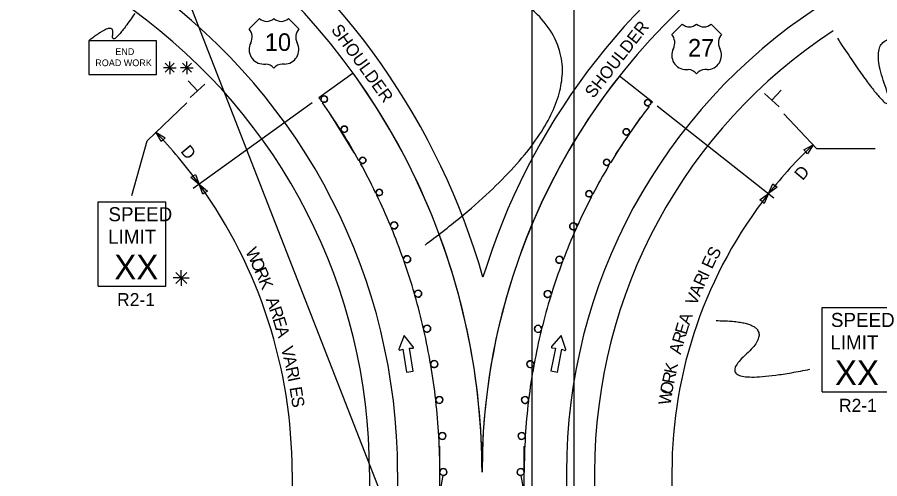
# Model space of a CAD drawing. Extents: x 16486 to 19506, y 5576 to 7023.
# Drawn here: x 16687.6 to 17178.1, y 6501.5 to 6764 of the extents above; entities that cross this region are included whole.
import ezdxf

# ---------------------------------------------------------------- set-up
doc = ezdxf.new("R2010")
doc.units = 0
for name, color, linetype in [('ALI_LEGAL_EX', 7, 'Continuous'), ('Level 3', 7, 'Continuous'), ('MT_SCRATCH_LEVEL_A', 7, 'Continuous'), ('MT_SCRATCH_LEVEL_E', 7, 'Continuous'), ('PAVT_EDGE_EX', 7, 'Continuous'), ('TRAFFIC_SIGNS_PR', 7, 'Continuous'), ('TYPICAL_EX', 7, 'Continuous'), ('TYPICAL_TEXT_DIMEN_PR', 7, 'Continuous')]:
    doc.layers.add(name, color=color, linetype=linetype)

msp = doc.modelspace()

# ---------------------------------------------------------------- linework, layer by layer
at = {"layer": 'ALI_LEGAL_EX'}
for p, q in [((16687.64, 7022.55), (16909.67, 6454.18)), ((16980.24, 6998.86), (16980.24, 6180.72)), ((17004.24, 6998.86), (17004.24, 6180.72)), ((16980.24, 6946.95), (16980.24, 6083.04)), ((17004.24, 6946.95), (17004.24, 6083.04))]:
    msp.add_line(p, q, dxfattribs=at)
for points in [[(16879.14, 6687.34), (16865.91, 6708.56)], [(16879.14, 6687.34), (16865.91, 6708.56)], [(17028.03, 6686.21), (17042.15, 6706.84)], [(17028.03, 6686.21), (17042.15, 6706.84)], [(16927.96, 6495.08), (16927.96, 6520.08)], [(16975.96, 6495.08), (16975.96, 6520.08)]]:
    msp.add_lwpolyline(points, dxfattribs=at)
at = {"layer": 'Level 3'}
msp.add_line((16843.96, 6505.27), (16843.96, 6497.36), dxfattribs=at)
at = {"layer": 'MT_SCRATCH_LEVEL_A'}
for points in [[(16878.71, 6732.17), (16859.24, 6718.13)], [(17048.92, 6715.72), (17030.07, 6730.57)], [(16859.73, 6717.44), (16860.41, 6717.44)], [(16861.61, 6715.71), (16861.18, 6715.41)], [(17047.92, 6715.51), (17048.77, 6715.53)], [(17047.03, 6713.3), (17046.58, 6713.66)], [(16871.46, 6700.06), (16871.86, 6700.32)], [(16872.87, 6698.7), (16872.47, 6698.45)], [(17035.06, 6696.83), (17034.64, 6697.12)], [(17035.78, 6698.8), (17036.21, 6698.5)], [(16881.95, 6682.41), (16882.33, 6682.62)], [(16883.16, 6681.09), (16882.8, 6680.89)], [(17024.66, 6681.5), (17025.05, 6681.26)], [(17024.1, 6679.68), (17023.71, 6679.91)], [(16891.44, 6664.19), (16891.78, 6664.35)], [(16892.46, 6662.95), (16892.12, 6662.78)], [(17014.19, 6661.91), (17013.83, 6662.09)], [(17014.6, 6663.56), (17014.96, 6663.37)], [(16899.86, 6645.53), (16900, 6645.59)], [(16900.59, 6644.18), (16900.44, 6644.12)], [(17005.33, 6643.5), (17005.17, 6643.57)], [(17005.83, 6645.05), (17005.99, 6644.98)], [(16907.24, 6626.34), (16907.35, 6626.37)], [(16907.78, 6625.13), (16907.68, 6625.09)], [(16997.62, 6624.68), (16997.5, 6624.72)], [(16997.99, 6626.04), (16998.11, 6625.99)], [(16913.53, 6606.76), (16913.61, 6606.78)], [(16913.91, 6605.72), (16913.83, 6605.7)], [(16991.05, 6605.43), (16990.96, 6605.46)], [(16991.31, 6606.59), (16991.4, 6606.56)], [(16918.7, 6586.85), (16918.76, 6586.87)], [(16918.95, 6586), (16918.9, 6585.99)], [(16985.64, 6585.83), (16985.59, 6585.85)], [(16985.81, 6586.77), (16985.87, 6586.75)], [(16922.74, 6566.69), (16922.78, 6566.69)], [(16922.89, 6566.04), (16922.86, 6566.03)], [(16981.42, 6565.94), (16981.38, 6565.95)], [(16981.51, 6566.65), (16981.55, 6566.65)], [(16925.64, 6546.33), (16925.66, 6546.33)], [(16925.71, 6545.89), (16925.69, 6545.88)], [(16978.39, 6545.84), (16978.37, 6545.84)], [(16978.43, 6546.32), (16978.45, 6546.31)], [(16927.38, 6525.83), (16927.39, 6525.83)], [(16927.4, 6525.61), (16927.39, 6525.61)], [(16976.57, 6525.59), (16976.56, 6525.59)], [(16976.58, 6525.83), (16976.58, 6525.83)], [(16927.96, 6505.27), (16927.97, 6505.27)], [(16975.96, 6505.27), (16975.96, 6505.27)], [(16929.62, 6503.3), (16927.96, 6493.83), (16975.96, 6493.83), (16974.3, 6503.3)]]:
    msp.add_lwpolyline(points, dxfattribs=at)
for centre, radius, start, end in [((16563.96, 6505.27), 388, 22.8554, 35.7873), ((17315.96, 6505.27), 364, 141.7598, 180), ((16563.96, 6505.27), 364, 35.6537, 35.7873), ((16862.21, 6717.41), 1.8, 0, 179.0978), ((16563.96, 6505.27), 364, 32.3536, 35.2603), ((16862.21, 6717.41), 1.8, 250.5205, 0), ((17046.13, 6715.4), 1.8, 3.5129, 180), ((17046.13, 6715.4), 1.8, 180, 284.5518), ((17315.96, 6505.27), 340, 141.7598, 141.7992), ((17315.96, 6505.27), 340, 142.2759, 145.3661), ((16873.66, 6700.32), 1.8, 0, 180), ((17033.98, 6698.8), 1.8, 0, 180), ((16563.96, 6505.27), 364, 29.1198, 32.0533), ((16873.66, 6700.32), 1.8, 244.1065, 0), ((17315.96, 6505.27), 340, 145.7074, 148.8275), ((17033.98, 6698.8), 1.8, 180, 291.4148), ((16884.13, 6682.62), 1.8, 0, 180), ((16563.96, 6505.27), 364, 25.8855, 28.8467), ((16884.13, 6682.62), 1.8, 237.6934, 0), ((17022.86, 6681.5), 1.8, 0, 180), ((17022.86, 6681.5), 1.8, 180, 298.2766), ((17315.96, 6505.27), 340, 149.1383, 152.2895), ((16893.58, 6664.35), 1.8, 0, 180), ((16563.96, 6505.27), 364, 22.663, 25.6406), ((16893.58, 6664.35), 1.8, 231.2811, 0), ((17315.96, 6505.27), 340, 152.5687, 155.7382), ((17012.8, 6663.56), 1.8, 0, 180), ((17012.8, 6663.56), 1.8, 180, 305.1374), ((16563.96, 6505.27), 388, 0, 22.8554), ((16563.96, 6505.27), 388, 0, 22.8554), ((16563.96, 6505.27), 388, 0, 22.8554), ((16902, 6645.59), 2, 0, 180), ((17003.83, 6645.05), 2, 0, 180), ((16563.96, 6505.27), 364, 19.4261, 22.4229), ((16902, 6645.59), 2, 224.8459, 0), ((17315.96, 6505.27), 340, 156.0121, 159.2032), ((17003.83, 6645.05), 2, 180, 312.0242), ((16909.35, 6626.37), 2, 0, 180), ((16995.99, 6626.04), 2, 0, 180), ((16563.96, 6505.27), 364, 16.189, 19.219), ((16909.35, 6626.37), 2, 218.4379, 0), ((17315.96, 6505.27), 340, 159.4399, 162.6687), ((16995.99, 6626.04), 2, 180, 318.8797), ((16915.61, 6606.78), 2, 0, 180), ((16989.31, 6606.59), 2, 0, 180), ((16563.96, 6505.27), 364, 12.9515, 16.0153), ((16915.61, 6606.78), 2, 212.0306, 0), ((17315.96, 6505.27), 340, 162.8672, 166.1345), ((16989.31, 6606.59), 2, 180, 325.7344), ((16920.75, 6586.87), 2, 0, 180), ((16983.81, 6586.77), 2, 0, 180), ((16563.96, 6505.27), 364, 9.7138, 12.8119), ((16920.75, 6586.87), 2, 205.6238, 0), ((17315.96, 6505.27), 340, 166.2942, 169.6006), ((16983.81, 6586.77), 2, 180, 332.5884), ((16924.78, 6566.69), 2, 0, 180), ((16979.51, 6566.65), 2, 0, 180), ((16563.96, 6505.27), 364, 6.476, 9.6087), ((16924.78, 6566.69), 2, 199.2175, 0), ((16979.51, 6566.65), 2, 180, 339.4418), ((17315.96, 6505.27), 340, 169.7209, 173.067), ((16927.66, 6546.33), 2, 0, 180), ((16563.96, 6505.27), 364, 3.238, 6.4057), ((16927.66, 6546.33), 2, 192.8115, 0), ((16976.43, 6546.32), 2, 0, 180), ((16976.43, 6546.32), 2, 180, 346.2947), ((17315.96, 6505.27), 340, 173.1474, 176.5334), ((16929.39, 6525.83), 2, 0, 180), ((16563.96, 6505.27), 364, 0, 3.2028), ((16929.39, 6525.83), 2, 186.4057, 0), ((16974.58, 6525.83), 2, 0, 180), ((16974.58, 6525.83), 2, 180, 353.1474), ((17315.96, 6505.27), 340, 176.5737, 180), ((16929.97, 6505.27), 2, 0, 180), ((16929.97, 6505.27), 2, 260.0595, 0), ((16973.96, 6505.27), 2, 0, 180), ((16973.96, 6505.27), 2, 180, 279.941)]:
    msp.add_arc(centre, radius, start, end, dxfattribs=at)
at = {"layer": 'MT_SCRATCH_LEVEL_E'}
for p, q in [((16907.63, 6583.04), (16904.71, 6575.24)), ((16912.87, 6576.54), (16907.63, 6583.04)), ((16996.96, 6582.95), (16991.53, 6576.64)), ((16999.63, 6575.05), (16996.96, 6582.95)), ((16905.29, 6574.64), (16907, 6575.23)), ((16907, 6575.23), (16909.09, 6562.14)), ((16912.78, 6562.73), (16910.7, 6575.82)), ((16910.7, 6575.82), (16912.5, 6575.79)), ((16993.67, 6575.84), (16991.12, 6562.83)), ((16991.87, 6575.87), (16993.67, 6575.84)), ((16994.79, 6562.11), (16997.34, 6575.12)), ((16997.34, 6575.12), (16999.03, 6574.47)), ((16909.09, 6562.14), (16912.78, 6562.73)), ((16991.12, 6562.83), (16994.79, 6562.11))]:
    msp.add_line(p, q, dxfattribs=at)
for centre, start, end in [((16905.15, 6575.08), 159.4773, 289.0163), ((16912.5, 6576.25), 269.0886, 38.8256), ((16991.88, 6576.34), 139.3091, 268.8481), ((16999.18, 6574.91), 248.9205, 18.6574)]:
    msp.add_arc(centre, 0.463, start, end, dxfattribs=at)
at = {"layer": 'PAVT_EDGE_EX'}
for p, q in [((16887.96, 6505.27), (16887.96, 6073.13)), ((16903.96, 6505.27), (16903.96, 6073.13)), ((16999.96, 6505.27), (16999.96, 6073.13)), ((17015.96, 6505.27), (17015.96, 6073.13))]:
    msp.add_line(p, q, dxfattribs=at)
for centre, radius, start, end in [((16563.96, 6505.27), 404, 15.917, 54.2283), ((17315.96, 6505.27), 380, 123.1879, 163.0483), ((16563.96, 6505.27), 388, 0, 54.2283), ((17315.96, 6505.27), 364, 123.1879, 180), ((16563.96, 6505.27), 340, 0, 54.2283), ((17315.96, 6505.27), 316, 123.1879, 180), ((16563.96, 6505.27), 324, 0, 54.2283), ((17315.96, 6505.27), 300, 123.1879, 180), ((17315.96, 6505.27), 300, 180, 180.00000277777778)]:
    msp.add_arc(centre, radius, start, end, dxfattribs=at)
at = {"layer": 'TRAFFIC_SIGNS_PR'}
for p, q in [((16733.73, 6659.1), (16772.13, 6659.1)), ((16733.73, 6611.1), (16733.73, 6659.1)), ((16772.13, 6611.1), (16772.13, 6659.1)), ((16733.73, 6611.1), (16772.13, 6611.1)), ((17145.34, 6598.96), (17183.74, 6598.96)), ((17145.34, 6550.96), (17145.34, 6598.96)), ((17145.34, 6550.96), (17183.74, 6550.96))]:
    msp.add_line(p, q, dxfattribs=at)
msp.add_lwpolyline([(16728.41, 6731.44), (16766.81, 6731.44), (16766.81, 6750.64), (16728.41, 6750.64)], close=True, dxfattribs=at)
for centre, radius in [((16862.21, 6717.41), 1.8), ((17046.13, 6715.4), 1.8), ((16873.66, 6700.32), 1.8), ((17033.98, 6698.8), 1.8), ((16884.13, 6682.62), 1.8), ((17022.86, 6681.5), 1.8), ((16893.58, 6664.35), 1.8), ((17012.8, 6663.56), 1.8), ((16902, 6645.59), 2), ((17003.83, 6645.05), 2), ((16909.35, 6626.37), 2), ((16995.99, 6626.04), 2), ((16915.61, 6606.78), 2), ((16989.31, 6606.59), 2), ((16920.75, 6586.87), 2), ((16983.81, 6586.77), 2), ((16924.78, 6566.69), 2), ((16979.51, 6566.65), 2), ((16927.66, 6546.33), 2), ((16976.43, 6546.32), 2), ((16929.39, 6525.83), 2), ((16974.58, 6525.83), 2), ((16929.97, 6505.27), 2), ((16973.96, 6505.27), 2)]:
    msp.add_circle(centre, radius, dxfattribs=at)
at = {"layer": 'TYPICAL_EX'}
for p, q in [((16819.47, 6757.43), (16825.37, 6763.33)), ((16847.77, 6757.43), (16841.88, 6763.33)), ((17059.84, 6754.25), (17065.74, 6760.14)), ((17088.14, 6754.25), (17082.25, 6760.14)), ((16827.72, 6737.37), (16828.9, 6737.37)), ((16839.53, 6737.37), (16838.35, 6737.37)), ((17068.09, 6734.19), (17069.27, 6734.19)), ((17079.9, 6734.19), (17078.72, 6734.19))]:
    msp.add_line(p, q, dxfattribs=at)
for centre, radius, start, end in [((16829.5, 6767.62), 5.96, 226.1404, 313.8596), ((16837.75, 6767.62), 5.96, 226.1404, 313.8596), ((17069.87, 6764.44), 5.96, 226.1404, 313.8596), ((17078.12, 6764.44), 5.96, 226.1404, 313.8596), ((16813.89, 6752.71), 7.31, 333.0977, 40.1936), ((16853.36, 6752.71), 7.31, 139.8064, 206.9023), ((17054.26, 6749.53), 7.31, 333.0977, 40.1936), ((17093.73, 6749.53), 7.31, 139.8064, 206.9023), ((16827.73, 6745.61), 8.24, 152.6698, 269.9013), ((16839.51, 6745.61), 8.24, 270.0987, 27.3302), ((17068.1, 6742.43), 8.24, 152.6698, 269.9013), ((17079.88, 6742.43), 8.24, 270.0987, 27.3302), ((16828.91, 6731.46), 5.91, 37.1038, 90.1385), ((16838.33, 6731.46), 5.91, 89.8615, 142.8962), ((17069.28, 6728.28), 5.91, 37.1038, 90.1385), ((17078.7, 6728.28), 5.91, 89.8615, 142.8962)]:
    msp.add_arc(centre, radius, start, end, dxfattribs=at)
at = {"layer": 'TYPICAL_TEXT_DIMEN_PR'}
for p, q in [((16774.36, 6735.26), (16770.73, 6735.26)), ((16771.81, 6737.81), (16776.91, 6732.71)), ((16776.91, 6737.81), (16771.81, 6732.71)), ((16774.36, 6735.26), (16774.36, 6738.82)), ((16774.36, 6735.26), (16776.91, 6735.26)), ((16774.36, 6735.26), (16777.94, 6735.26)), ((16774.36, 6735.26), (16774.36, 6731.66)), ((16784.1, 6735.26), (16780.47, 6735.26)), ((16781.55, 6737.81), (16786.65, 6732.71)), ((16786.65, 6737.81), (16781.55, 6732.71)), ((16784.1, 6735.26), (16784.1, 6738.82)), ((16784.1, 6735.26), (16786.65, 6735.26)), ((16784.1, 6735.26), (16787.68, 6735.26)), ((16784.1, 6735.26), (16784.1, 6731.66)), ((16790.19, 6722.15), (16784.91, 6727.87)), ((16794.32, 6725.97), (16786.06, 6718.34)), ((17120.89, 6712.97), (17112.65, 6720.63)), ((17116.77, 6716.8), (17122.07, 6722.51)), ((16783.99, 6715.23), (16761.5, 6693.76)), ((16855.45, 6715.4), (16787.66, 6666.53)), ((17051.63, 6713.58), (17117.9, 6661.36)), ((17123.65, 6709.11), (17142.26, 6689.38)), ((16769.45, 6693.24), (16766.54, 6698.57)), ((16766.54, 6698.57), (16771.72, 6695.41)), ((16752.8, 6662.58), (16761.5, 6693.76)), ((16770.58, 6694.33), (16769.45, 6693.24)), ((16771.72, 6695.41), (16770.58, 6694.33)), ((17134.94, 6688.6), (17140.28, 6691.48)), ((17140.28, 6691.48), (17137.1, 6686.31)), ((17136.02, 6687.46), (17134.94, 6688.6)), ((17137.1, 6686.31), (17136.02, 6687.46)), ((17142.26, 6689.38), (17175.46, 6689.38)), ((17142.26, 6689.38), (17175.46, 6689.38)), ((17142.26, 6689.38), (17175.46, 6689.38)), ((16786.44, 6672.79), (16787.71, 6673.71)), ((16791.14, 6668.95), (16786.44, 6672.79)), ((16787.71, 6673.71), (16788.99, 6674.62)), ((16788.99, 6674.62), (16791.14, 6668.95)), ((16793.24, 6663.33), (16791.08, 6669)), ((16791.08, 6669), (16795.78, 6665.16)), ((17114.89, 6663.73), (17117.29, 6669.3)), ((17119.76, 6667.36), (17114.89, 6663.73)), ((17117.29, 6669.3), (17118.52, 6668.33)), ((17118.52, 6668.33), (17119.76, 6667.36)), ((16794.51, 6664.24), (16793.24, 6663.33)), ((16795.78, 6665.16), (16794.51, 6664.24)), ((17110.03, 6660.09), (17114.89, 6663.73)), ((17114.89, 6663.73), (17112.5, 6658.15)), ((17111.27, 6659.12), (17110.03, 6660.09)), ((17112.5, 6658.15), (17111.27, 6659.12)), ((17006.48, 6646.05), (17004.65, 6646.88)), ((16777.73, 6618.9), (16784.11, 6612.52)), ((16784.11, 6618.9), (16777.73, 6612.52)), ((16780.92, 6615.71), (16780.92, 6620.17)), ((16780.92, 6615.71), (16776.39, 6615.71)), ((16780.92, 6615.71), (16784.11, 6615.71)), ((16780.92, 6615.71), (16785.4, 6615.71)), ((16780.92, 6615.71), (16780.92, 6611.21)), ((17059.96, 6505.27), (17059.96, 6493.83))]:
    msp.add_line(p, q, dxfattribs=at)
for centre, radius, start, end in [((16563.96, 6505.27), 280, 35.772, 43.6576), ((17315.96, 6505.27), 256, 133.334, 141.7597), ((16563.96, 6505.27), 280, 0, 35.7873), ((17315.96, 6505.27), 256, 141.7599, 180)]:
    msp.add_arc(centre, radius, start, end, dxfattribs=at)
for points in [[(16919.56, 6634.43), (17052.11, 6732.96), (16867.22, 6832.32), (16990.41, 6903.66)], [(16754.42, 6766.08), (16740.6, 6745.78), (16743.35, 6762.56), (16728.41, 6750.64)], [(17154.04, 6752.02), (17192.28, 6693.85), (17169.06, 6759.55), (17198.42, 6749.97)], [(17085.14, 6591.42), (17123.38, 6591.42), (17079.79, 6551.95), (17138.43, 6563.79)]]:
    msp.add_open_spline(points, degree=2, dxfattribs=at)

# ---------------------------------------------------------------- texts
at = {"layer": 'TRAFFIC_SIGNS_PR'}
for s, height, p in [('END', 3.831, (16743.41, 6742.56)), ('ROAD WORK', 3.831, (16732.01, 6736.18)), ('SPEED', 8, (16739.5, 6647.96)), ('LIMIT', 8, (16739.34, 6635.16)), ('XX', 14.031, (16742.84, 6614.86)), ('R2-1', 7.44, (16744.41, 6599.66)), ('SPEED', 8, (17150.37, 6587.82)), ('LIMIT', 8, (17150.04, 6575.02)), ('XX', 14.031, (17152.65, 6554.72)), ('R2-1', 7.44, (17154.95, 6539.52))]:
    msp.add_text(s, height=height, dxfattribs=at).set_placement(p)
at = {"layer": 'TYPICAL_EX'}
for s, p in [('10', (16828.46, 6744.86)), ('27', (17069.1, 6741.67))]:
    msp.add_text(s, height=10, dxfattribs=at).set_placement(p)
at = {"layer": 'TYPICAL_TEXT_DIMEN_PR'}
for s, rotation, p in [('SHOULDER', 305.9489, (16865.82, 6756.88)), ('SHOULDER', 52.0184, (17015.32, 6717.47)), ('D', 310, (16780.18, 6687.6)), ('D', 50, (17134.31, 6670.75)), ('W', 296.9052, (16817.17, 6630.85)), ('S', 62.4974, (17085.49, 6625.66)), ('O', 294.3428, (16819.93, 6625.07)), ('E', 65.1772, (17082.8, 6620.36)), ('R', 294.3428, (16822.31, 6619.81)), ('R', 65.1772, (17078.14, 6610.28)), ('I', 65.1772, (17080.65, 6615.7)), ('K', 291.7804, (16824.72, 6614.21)), ('V', 67.857, (17073.76, 6599.52)), ('A', 67.857, (17075.86, 6604.68)), ('A', 289.218, (16828.94, 6603.5)), ('R', 289.218, (16830.84, 6598.05)), ('E', 286.6556, (16832.8, 6592.39)), ('A', 70.5368, (17069.88, 6588.64)), ('E', 73.2167, (17068.14, 6583.06)), ('A', 286.6556, (16834.4, 6587.07)), ('R', 73.2167, (17066.51, 6577.66)), ('A', 75.8965, (17064.93, 6571.82)), ('V', 284.0932, (16837.54, 6575.88)), ('A', 284.0932, (16838.89, 6570.48)), ('R', 281.5308, (16840.23, 6564.56)), ('K', 78.5763, (17062.28, 6560.7)), ('I', 281.5308, (16841.43, 6558.66)), ('R', 78.5763, (17061.14, 6555.06)), ('E', 278.9684, (16842.43, 6553.32)), ('O', 81.2562, (17060.06, 6549.1)), ('W', 81.2562, (17059.13, 6543.07)), ('S', 278.9684, (16843.32, 6547.73))]:
    msp.add_text(s, height=7, rotation=rotation, dxfattribs=at).set_placement(p)

doc.saveas('drawing.dxf')
